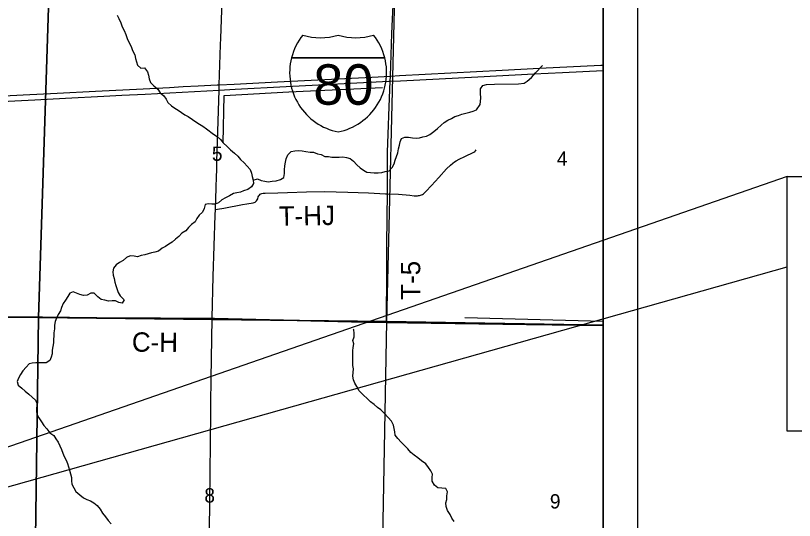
# Model space of a CAD drawing. Extents: x 0 to 42, y 0 to 22.
# Drawn here: x 7.178 to 9.46, y 17.887 to 19.367 of the extents above; entities that cross this region are included whole.
import ezdxf

# ---------------------------------------------------------------- set-up
doc = ezdxf.new("R2010")
doc.units = 0
for name, color, linetype in [('Default', 7, 'Continuous'), ('GM_X_County_Road', 7, 'Continuous'), ('GM_X_County_Road_Text', 7, 'Continuous'), ('GM_X_Interchange_Ramps', 7, 'Continuous'), ('GM_X_Interstate_Location', 7, 'Continuous'), ('GM_X_Interstate_Route', 7, 'Continuous'), ('GM_X_Interstate_Shield', 7, 'Continuous'), ('GM_X_Minor_River', 7, 'Continuous'), ('GM_X_Section', 7, 'Continuous'), ('GM_X_Section_Text', 7, 'Continuous'), ('GM_X_Township_Road', 7, 'Continuous'), ('GM_X_Township_Road_Text', 7, 'Continuous'), ('SH_Data', 7, 'Continuous'), ('SH_Text', 7, 'Continuous')]:
    doc.layers.add(name, color=color, linetype=linetype)

msp = doc.modelspace()

# ---------------------------------------------------------------- linework, layer by layer
at = {"layer": 'Default'}
for points in [[(8.9, 18.4589), (8.9, 19.4571), (8.2893, 19.4656), (8.2652, 18.4704)], [(8.9, 17.4474), (8.9, 18.4589), (8.2652, 18.4704), (8.2465, 17.4593)]]:
    msp.add_lwpolyline(points, close=True, dxfattribs=at)
at = {"layer": 'GM_X_County_Road'}
for points in [[(7.7638, 18.7981), (7.7647, 18.8288), (7.7663, 18.8628), (7.767, 18.8942), (7.7675, 18.9147), (7.7681, 18.9395), (7.7708, 19.0266), (7.7744, 19.148), (7.7744, 19.1508), (7.7749, 19.1634), (7.7787, 19.2813), (7.7797, 19.2999), (7.783, 19.4088), (7.7844, 19.4398), (7.7862, 19.4646), (7.787, 19.4762)], [(7.7538, 18.4779), (7.7538, 18.4805), (7.7575, 18.6015), (7.763, 18.7815), (7.7638, 18.7981)], [(6.7429, 18.4872), (6.838, 18.4861), (7.1395, 18.4831), (7.2576, 18.4819), (7.4161, 18.4806), (7.6026, 18.4793), (7.7538, 18.4779)], [(7.7411, 17.5101), (7.7414, 17.535), (7.7418, 17.5645), (7.7428, 17.6359), (7.7449, 17.7788), (7.7459, 17.8564), (7.747, 17.9433), (7.7482, 18.0241), (7.7492, 18.1172), (7.7494, 18.1358), (7.7499, 18.1824), (7.7503, 18.229), (7.7513, 18.3035), (7.7538, 18.4779)], [(7.7538, 18.4779), (7.7611, 18.4778), (8.0035, 18.4727), (8.2024, 18.4685), (8.2649, 18.4674)], [(8.2649, 18.4674), (8.3268, 18.4663), (8.6749, 18.4614), (8.9, 18.4584)]]:
    msp.add_lwpolyline(points, dxfattribs=at)
at = {"layer": 'GM_X_Interchange_Ramps'}
for points in [[(6.2823, 19.4965), (6.2766, 19.154), (6.2763, 19.1388), (6.2658, 18.6234), (6.2632, 18.4934), (6.272, 18.4933), (6.388, 18.4919), (6.5797, 18.4897), (6.7165, 18.488), (6.7427, 18.4877), (6.8377, 18.4866), (7.1392, 18.4837), (7.2573, 18.4825), (7.4159, 18.4812), (7.6024, 18.4799), (7.7535, 18.4785), (7.7609, 18.4784), (8.0033, 18.4733), (8.2022, 18.4691), (8.2646, 18.468), (8.3265, 18.4669), (8.6747, 18.462), (8.9, 18.4589), (8.9, 20.9)], [(8.9, 14.1), (8.9, 18.4589), (8.6747, 18.462), (8.3265, 18.4669), (8.2646, 18.468), (8.2022, 18.4691), (8.0033, 18.4733), (7.7609, 18.4784), (7.7535, 18.4785), (7.6024, 18.4799), (7.4159, 18.4812), (7.2573, 18.4825), (7.1392, 18.4837)]]:
    msp.add_lwpolyline(points, dxfattribs=at)
at = {"layer": 'GM_X_Interstate_Route'}
for points in [[(7.0672, 19.1271), (7.2007, 19.1346), (7.3, 19.1392), (7.4118, 19.1451), (7.5516, 19.1522), (7.6292, 19.1562), (7.6696, 19.1585), (7.713, 19.1605), (7.7689, 19.1632), (7.7749, 19.1634), (7.8186, 19.1655), (7.9459, 19.1719), (8.2223, 19.1862), (8.2763, 19.1891), (8.3031, 19.1905), (8.6043, 19.2062), (8.7129, 19.2121), (8.893, 19.2213), (8.9, 19.2216)], [(7.098, 19.1128), (7.2346, 19.1201), (7.3247, 19.1247), (7.4365, 19.1304), (7.4893, 19.1332), (7.5576, 19.1365), (7.6663, 19.1422), (7.7744, 19.148), (7.8215, 19.1505), (7.9705, 19.1585), (8.1041, 19.1651), (8.2717, 19.1739), (8.2757, 19.1741), (8.3057, 19.1754), (8.5324, 19.1873), (8.6969, 19.1954), (8.7808, 19.1999), (8.9, 19.2058)]]:
    msp.add_lwpolyline(points, dxfattribs=at)
at = {"layer": 'GM_X_Interstate_Shield'}
for p, q in [((7.9866, 19.2429), (8.2599, 19.2429)), ((8.2599, 19.2429), (7.9866, 19.2429)), ((8.2599, 19.2429), (7.9866, 19.2429))]:
    msp.add_line(p, q, dxfattribs=at)
for centre, start, end in [((8.1588, 19.1994), 141.669, 165.8066), ((8.0714, 19.4793), 253.0091, 286.9909), ((8.1751, 19.4793), 253.0091, 286.9909), ((8.0877, 19.1994), 14.1934, 38.331), ((8.1588, 19.1994), 165.8066, 258.463), ((8.0877, 19.1994), 281.537, 14.1934)]:
    msp.add_arc(centre, 0.1776, start, end, dxfattribs=at)
at = {"layer": 'GM_X_Minor_River'}
msp.add_line((8.9, 18.4705), (8.4943, 18.4812), dxfattribs=at)
for points in [[(7.4761, 19.3675), (7.4804, 19.3579), (7.4862, 19.3457), (7.4905, 19.3338), (7.4964, 19.3227), (7.5007, 19.3108), (7.5054, 19.2997), (7.5108, 19.2871), (7.5163, 19.2756), (7.5206, 19.2645), (7.5275, 19.2514), (7.5292, 19.2407), (7.5328, 19.2308), (7.5352, 19.2213), (7.5453, 19.2127), (7.5555, 19.2136), (7.5648, 19.2017), (7.568, 19.1917), (7.5693, 19.1815), (7.5732, 19.1708), (7.5833, 19.1611), (7.5948, 19.1506), (7.6022, 19.1405), (7.6126, 19.1316), (7.6196, 19.1216), (7.624, 19.1116), (7.6348, 19.1023), (7.6445, 19.0957), (7.6546, 19.0898), (7.6643, 19.0823), (7.674, 19.0757)], [(8.541, 19.1243), (8.5402, 19.1395), (8.5405, 19.152), (8.5475, 19.1614), (8.5581, 19.1642), (8.5813, 19.1652), (8.6518, 19.1665), (8.6681, 19.1681), (8.6773, 19.1739), (8.69, 19.1851), (8.7017, 19.1989), (8.722, 19.2207)], [(7.786, 18.9937), (7.7892, 19.1326), (7.9784, 19.1428), (8.253, 19.1559)], [(7.8739, 18.8845), (7.8873, 18.888), (7.8974, 18.8836), (7.908, 18.8811), (7.9186, 18.8794), (7.93, 18.8811), (7.9421, 18.8827), (7.9543, 18.8866), (7.9639, 18.8921), (7.9656, 18.9039), (7.9659, 18.9149), (7.9672, 18.9259), (7.969, 18.9372), (7.9711, 18.9471), (7.9755, 18.958), (7.9855, 18.9684), (7.9961, 18.9697), (8.0072, 18.971), (8.0181, 18.9704), (8.0283, 18.9687), (8.0415, 18.9665), (8.0514, 18.9663), (8.0627, 18.9612), (8.074, 18.959), (8.0845, 18.9539), (8.0947, 18.9537), (8.1045, 18.9516), (8.1151, 18.9514), (8.1261, 18.9519), (8.1367, 18.9528), (8.1473, 18.9511), (8.1582, 18.9475), (8.1683, 18.94), (8.1783, 18.9296), (8.188, 18.9207), (8.1977, 18.9133), (8.2078, 18.9081), (8.229, 18.9054), (8.2407, 18.9059), (8.2514, 18.9069), (8.2609, 18.9093), (8.2723, 18.9118), (8.2816, 18.9214), (8.2871, 18.9323), (8.29, 18.9425), (8.2943, 18.9531), (8.298, 18.9644), (8.3005, 18.9761), (8.3034, 18.9867), (8.3051, 18.9965), (8.3087, 19.0063), (8.319, 19.0107), (8.3296, 19.0101), (8.3413, 19.0079), (8.3519, 19.0074), (8.3614, 19.0087), (8.3713, 19.0108), (8.382, 19.0136), (8.3923, 19.0179), (8.4034, 19.0264), (8.4142, 19.0353), (8.4247, 19.0458), (8.4343, 19.0532), (8.4446, 19.0602), (8.455, 19.0653), (8.4653, 19.0711), (8.476, 19.074), (8.4855, 19.0772), (8.4977, 19.0804), (8.5091, 19.0835), (8.5191, 19.0864), (8.5288, 19.0903), (8.5393, 19.1058), (8.541, 19.1243)], [(7.674, 19.0757), (7.6837, 19.0706), (7.6961, 19.0623), (7.7058, 19.0553), (7.7166, 19.0479), (7.7271, 19.042), (7.7376, 19.0342), (7.7585, 19.0193), (7.7686, 19.0126), (7.7786, 19.0033), (7.786, 18.9937), (7.7979, 18.9824), (7.8079, 18.9731), (7.8199, 18.9634), (7.8295, 18.9541), (7.8373, 18.9444), (7.8477, 18.9355), (7.8562, 18.9254), (7.8659, 18.915), (7.8694, 18.9051), (7.8715, 18.8948), (7.8739, 18.8845), (7.8753, 18.8746), (7.8694, 18.8644), (7.8582, 18.8571), (7.8464, 18.8527), (7.8369, 18.8495), (7.8262, 18.8475), (7.8163, 18.8454), (7.8048, 18.8388), (7.793, 18.8329), (7.7826, 18.8263), (7.773, 18.8178), (7.7627, 18.8142), (7.7528, 18.8136), (7.743, 18.8146), (7.7335, 18.8125), (7.731, 18.8011), (7.7254, 18.7906), (7.7158, 18.7817), (7.7091, 18.772), (7.7044, 18.7618), (7.694, 18.7548), (7.6844, 18.7459), (7.6766, 18.7362), (7.6655, 18.7292), (7.6566, 18.7195), (7.6465, 18.7113), (7.6369, 18.7024), (7.6269, 18.6969), (7.6173, 18.6895), (7.6078, 18.6852), (7.5966, 18.6763), (7.5863, 18.6734), (7.5768, 18.6717), (7.5669, 18.6685), (7.557, 18.6657), (7.5459, 18.6636), (7.5356, 18.6597), (7.5254, 18.6614), (7.5137, 18.6628), (7.503, 18.6577), (7.493, 18.6484), (7.483, 18.6429), (7.473, 18.6362), (7.4649, 18.6265), (7.4635, 18.6155), (7.4637, 18.606), (7.4665, 18.5957), (7.4693, 18.585), (7.4714, 18.5751), (7.4786, 18.5552), (7.4848, 18.5456), (7.496, 18.5336), (7.4908, 18.5239), (7.481, 18.526), (7.4709, 18.5311), (7.4611, 18.5309), (7.4508, 18.53), (7.4395, 18.5329), (7.4289, 18.5342), (7.4192, 18.5428), (7.4081, 18.5529), (7.3982, 18.5527), (7.3875, 18.5468), (7.3773, 18.5463), (7.3667, 18.5488), (7.3569, 18.5535), (7.3468, 18.5571), (7.3372, 18.5532), (7.331, 18.543), (7.3239, 18.5322), (7.3177, 18.5224), (7.3122, 18.5115), (7.3093, 18.5013), (7.3026, 18.4901), (7.2975, 18.4795), (7.2939, 18.4697), (7.2925, 18.4595), (7.2919, 18.4481), (7.2902, 18.4372)], [(8.4633, 17.8838), (8.4564, 17.8942), (8.452, 17.9042), (8.4439, 17.9161), (8.44, 17.9276), (8.4387, 17.9383), (8.4419, 17.9488), (8.4418, 17.9595), (8.4439, 17.9708), (8.4384, 17.9804), (8.4267, 17.9818), (8.4157, 17.9831), (8.4053, 17.9906), (8.3987, 18.0021), (8.3985, 18.0127), (8.3995, 18.023), (8.3944, 18.0326), (8.3881, 18.0426), (8.3804, 18.053), (8.368, 18.0619), (8.3572, 18.0701), (8.3464, 18.0787), (8.3367, 18.0865), (8.3278, 18.0973), (8.3178, 18.1066), (8.3081, 18.1163), (8.2981, 18.1271), (8.2904, 18.1372), (8.2898, 18.1467), (8.2877, 18.1562), (8.2853, 18.1661), (8.2798, 18.1784), (8.2698, 18.1885), (8.2594, 18.2001), (8.2487, 18.2113), (8.239, 18.2179), (8.2293, 18.2269), (8.2181, 18.2347), (8.2084, 18.244), (8.1976, 18.2541), (8.1846, 18.2673), (8.1777, 18.2795), (8.1722, 18.2891), (8.1686, 18.2995), (8.1662, 18.3102), (8.1672, 18.3211), (8.1678, 18.331), (8.1664, 18.3409), (8.1659, 18.3519), (8.1665, 18.3618), (8.1663, 18.3717), (8.1665, 18.3838), (8.1671, 18.3937), (8.1696, 18.405), (8.1665, 18.4146), (8.1702, 18.4249), (8.1699, 18.4361), (8.1697, 18.4456), (8.1682, 18.4479)], [(7.2902, 18.4372), (7.2904, 18.4277), (7.2887, 18.4174), (7.2888, 18.4079), (7.2871, 18.3966), (7.2854, 18.386), (7.2848, 18.375), (7.2827, 18.3652), (7.2783, 18.3554), (7.2676, 18.3488), (7.2577, 18.3486), (7.2475, 18.3492), (7.2373, 18.349), (7.227, 18.3484), (7.2175, 18.3456), (7.209, 18.3359), (7.1993, 18.3251), (7.1926, 18.3146), (7.1867, 18.3041), (7.1827, 18.2943), (7.1852, 18.2836), (7.196, 18.2746), (7.206, 18.2657), (7.2168, 18.2571), (7.2265, 18.2482), (7.2366, 18.2396), (7.2413, 18.2285), (7.2392, 18.2172), (7.239, 18.2077), (7.2407, 18.1982), (7.2461, 18.1882), (7.2539, 18.1763), (7.2608, 18.1655), (7.2694, 18.1555), (7.2786, 18.1439), (7.2898, 18.1361), (7.2964, 18.126), (7.3027, 18.1161), (7.3074, 18.1053), (7.3128, 18.0946), (7.3164, 18.0846), (7.3204, 18.0743), (7.3262, 18.0636), (7.3306, 18.0536), (7.333, 18.0441), (7.3362, 18.0341), (7.3387, 18.0238), (7.3423, 18.0131), (7.3421, 18.0029), (7.343, 17.9934), (7.3485, 17.983), (7.3551, 17.9722), (7.3659, 17.9621), (7.3774, 17.9536), (7.3872, 17.9484), (7.3973, 17.9444), (7.4071, 17.9389), (7.4175, 17.9307), (7.4264, 17.9199), (7.4326, 17.9088), (7.4411, 17.8972), (7.4496, 17.8872), (7.4581, 17.8767)]]:
    msp.add_lwpolyline(points, dxfattribs=at)
at = {"layer": 'GM_X_Section'}
for points in [[(6.2834, 19.5071), (7.2774, 19.4824), (7.2453, 18.4817), (6.2631, 18.4885)], [(7.2774, 19.4824), (7.2872, 19.4822), (8.2893, 19.4656), (8.2652, 18.4704), (7.2453, 18.4817)], [(6.2631, 18.4885), (7.2453, 18.4817), (7.2316, 17.475), (6.2427, 17.4846)], [(7.2453, 18.4817), (8.2652, 18.4704), (8.2465, 17.4593), (7.2316, 17.475)]]:
    msp.add_lwpolyline(points, close=True, dxfattribs=at)
at = {"layer": 'GM_X_Township_Road'}
for points in [[(8.2675, 18.8442), (8.2678, 18.9193), (8.2683, 18.966), (8.2699, 19.0188), (8.2729, 19.0995), (8.2757, 19.1741), (8.2763, 19.1891), (8.281, 19.3136), (8.2853, 19.4191), (8.2867, 19.444), (8.2889, 19.4687)], [(8.2675, 18.8442), (8.2997, 18.8429), (8.3338, 18.8401), (8.3462, 18.8388), (8.3525, 18.8385), (8.3556, 18.8386), (8.3587, 18.8389), (8.3617, 18.8394), (8.3647, 18.8402), (8.3676, 18.8413), (8.3704, 18.8427), (8.373, 18.8444), (8.3755, 18.8463), (8.38, 18.8506), (8.3971, 18.8687), (8.418, 18.8918), (8.4412, 18.917), (8.4521, 18.9281), (8.4592, 18.9341), (8.4642, 18.9378), (8.4695, 18.9411), (8.4777, 18.9455), (8.4945, 18.9537), (8.5211, 18.9664), (8.5235, 18.9679), (8.525, 18.9692), (8.5258, 18.9705), (8.5277, 18.9735)], [(7.7638, 18.7981), (7.77, 18.7988), (7.7882, 18.8025), (7.8433, 18.8125), (7.8554, 18.8149), (7.8738, 18.818), (7.8769, 18.8188), (7.8797, 18.82), (7.8823, 18.8216), (7.8845, 18.8238), (7.8862, 18.8264), (7.8875, 18.8292), (7.8894, 18.8352), (7.8907, 18.8381), (7.8924, 18.8406), (7.8946, 18.8428), (7.8972, 18.8444), (7.9001, 18.8454), (7.9032, 18.8461), (7.9094, 18.8466), (7.9467, 18.8474), (7.9745, 18.8481), (8.0305, 18.8503), (8.0833, 18.8506), (8.1175, 18.8501), (8.1519, 18.8492), (8.2125, 18.8469), (8.2624, 18.8444), (8.2675, 18.8442)], [(8.2649, 18.4674), (8.2649, 18.4752), (8.2652, 18.5001), (8.2659, 18.587), (8.2664, 18.6802), (8.2669, 18.7889), (8.2675, 18.8324), (8.2675, 18.8442)]]:
    msp.add_lwpolyline(points, dxfattribs=at)
at = {"layer": 'SH_Data'}
for p, q in [((9, 21), (9, 14)), ((8.9, 20.9), (8.9, 14.1))]:
    msp.add_line(p, q, dxfattribs=at)
at = {"layer": 'SH_Text'}
for points in [[(9.439, 18.8951), (5.359, 17.4787), (9.439, 18.63)], [(9.439, 18.8951), (10.9983, 18.8951), (10.9983, 18.149), (9.439, 18.149)]]:
    msp.add_lwpolyline(points, close=True, dxfattribs=at)

# ---------------------------------------------------------------- texts
at = {"layer": 'GM_X_County_Road_Text'}
msp.add_text('C-H', height=0.05682, rotation=359.6023, dxfattribs=at).set_placement((7.5188, 18.3816))
at = {"layer": 'GM_X_Interstate_Location'}
for s in ['.', '-', ',']:
    msp.add_text(s, height=0.000189, dxfattribs=at).set_placement((8.1232, 19.1673))
msp.add_text('80', height=0.000189, rotation=0, dxfattribs=at).set_placement((8.0845, 19.1281))
at = {"layer": 'GM_X_Interstate_Shield'}
msp.add_text('80', height=0.11837, dxfattribs=at).set_placement((8.0505, 19.1053))
at = {"layer": 'GM_X_Section_Text'}
for s, p in [('5', (7.7533, 18.9409)), ('4', (8.7641, 18.9266)), ('8', (7.7312, 17.9396)), ('9', (8.7437, 17.9221))]:
    msp.add_text(s, height=0.0419, rotation=0, dxfattribs=at).set_placement(p)
at = {"layer": 'GM_X_Township_Road_Text'}
for s, rotation, p in [('T-HJ', 0.9903, (7.9498, 18.7502)), ('T-5', 90, (8.3639, 18.5337))]:
    msp.add_text(s, height=0.05682, rotation=rotation, dxfattribs=at).set_placement(p)

doc.saveas('drawing.dxf')
